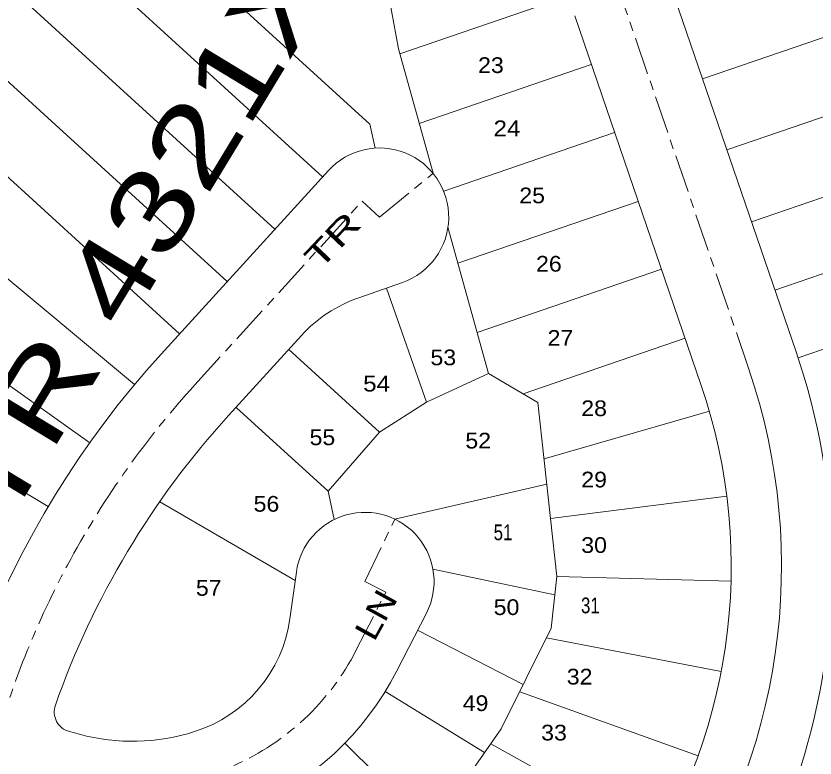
# Model space of a CAD drawing. Extents: x 6387474 to 6390971, y 1972046 to 1973920.
# Drawn here: x 6389237 to 6389745, y 1972779 to 1973251 of the extents above; entities that cross this region are included whole.
import ezdxf

# ---------------------------------------------------------------- set-up
doc = ezdxf.new("R2010")
doc.units = 0
doc.header["$LTSCALE"] = 4
doc.linetypes.add('LONG_DASH_SHORT_DASH', pattern=[9.9, 6, -1.2, 1.5, -1.2])
for name, color, linetype, lineweight in [('1', 7, 'Continuous', 13), ('2', 7, 'LONG_DASH_SHORT_DASH', 13), ('3', 7, 'Continuous', 13), ('4', 7, 'Continuous', 13)]:
    doc.layers.add(name, color=color, linetype=linetype, lineweight=lineweight)
doc.layers.add('7', color=7, linetype='Continuous')

msp = doc.modelspace()

# ---------------------------------------------------------------- linework, layer by layer
at = {"layer": '2'}
for p, q in [((6389702.592, 1973027.135), (6389622.235, 1973261.523)), ((6389467.811, 1973123.262), (6389501.879, 1973151.108)), ((6389458.497, 1972891.565), (6389477.608, 1972931.198)), ((6389471.847, 1972884.725), (6389458.497, 1972891.565)), ((6389453.054, 1972848.049), (6389471.847, 1972884.725))]:
    msp.add_line(p, q, dxfattribs=at)
msp.add_lwpolyline([(6389350.365, 1973016.66), (6389456.724, 1973133.366), (6389467.811, 1973123.262)], dxfattribs=at)
at = {"layer": '2', "linetype": 'Continuous'}
msp.add_arc((6389335.562, 1972901.304), 388, 270.34667, 18.92364, dxfattribs=at)
at = {"layer": '2'}
for centre, radius, start, end in [((6389771.658, 1972632.718), 570, 137.65572, 165.09236), ((6389310.662, 1972921.018), 160, 255.09194, 332.86738)]:
    msp.add_arc(centre, radius, start, end, dxfattribs=at)
at = {"layer": '3'}
for p, q in [((6389461.63, 1973182.312), (6389072.673, 1973536.784)), ((6389431.586, 1973148.835), (6389073.043, 1973475.589)), ((6389401.274, 1973115.575), (6389073.413, 1973414.367)), ((6389370.963, 1973082.315), (6389073.784, 1973353.146)), ((6389479.969, 1973230.272), (6389463.195, 1973318.918)), ((6389340.651, 1973049.055), (6389074.154, 1973291.925)), ((6389587.696, 1973263.794), (6389480.831, 1973227.157)), ((6389784.098, 1973249.169), (6389673.319, 1973211.19)), ((6389501.879, 1973151.108), (6389479.969, 1973230.272)), ((6389602.55, 1973220.269), (6389493.121, 1973182.753)), ((6389311.975, 1973016.765), (6389074.625, 1973214.186)), ((6389797.825, 1973203.344), (6389688.821, 1973165.973)), ((6389461.63, 1973182.312), (6389464.961, 1973167.167)), ((6389617.39, 1973176.982), (6389508.626, 1973139.694)), ((6389811.683, 1973157.078), (6389704.472, 1973120.322)), ((6389632.389, 1973133.232), (6389517.733, 1973093.924)), ((6389283.443, 1972979.771), (6389075.147, 1973127.843)), ((6389537.139, 1973023.81), (6389511.357, 1973116.959)), ((6389824.899, 1973112.959), (6389719.397, 1973076.789)), ((6389647.181, 1973090.087), (6389529.922, 1973049.886)), ((6389497.798, 1973005.508), (6389472.266, 1973078.188)), ((6389837.948, 1973069.396), (6389734.116, 1973033.799)), ((6389257.09, 1972939.344), (6389075.633, 1973047.475)), ((6389662.213, 1973046.242), (6389559.249, 1973010.943)), ((6389467.882, 1972986.489), (6389410.097, 1973039.15)), ((6389497.798, 1973005.508), (6389537.139, 1973023.81)), ((6389537.139, 1973023.81), (6389568.617, 1973005.492)), ((6389467.882, 1972986.489), (6389497.798, 1973005.508)), ((6389568.617, 1973005.492), (6389580.573, 1972894.731)), ((6389435.193, 1972948.919), (6389376.596, 1973002.321)), ((6389572.493, 1972969.58), (6389677.639, 1972999.893)), ((6389435.193, 1972948.919), (6389467.882, 1972986.489)), ((6389477.608, 1972931.198), (6389574.243, 1972953.372)), ((6389435.193, 1972948.919), (6389438.994, 1972931.007)), ((6389576.585, 1972931.671), (6389688.769, 1972945.817)), ((6389327.993, 1972942.301), (6389414.179, 1972892.316)), ((6389579.323, 1972883.05), (6389501.805, 1972899.342)), ((6389577.067, 1972861.964), (6389580.573, 1972894.731)), ((6389580.573, 1972894.731), (6389691.435, 1972891.766)), ((6389545.231, 1972797.842), (6389577.067, 1972861.964)), ((6389492.047, 1972860.553), (6389559.266, 1972826.11)), ((6389573.941, 1972855.667), (6389685.213, 1972834.366)), ((6389534.619, 1972782.798), (6389471.493, 1972821.75)), ((6389556.993, 1972821.533), (6389670.492, 1972780.647)), ((6389545.231, 1972797.842), (6389515.636, 1972755.89)), ((6389498.047, 1972737.54), (6389445.712, 1972788.797)), ((6389538.594, 1972788.433), (6389646.715, 1972728.329))]:
    msp.add_line(p, q, dxfattribs=at)
at = {"layer": '4'}
for p, q in [((6389732.862, 1973037.513), (6389652.505, 1973271.901)), ((6389672.321, 1973016.757), (6389591.964, 1973251.145)), ((6389328.931, 1973036.194), (6389435.29, 1973152.9)), ((6389454.089, 1973071.803), (6389482.394, 1973081.746)), ((6389371.799, 1972997.126), (6389418.209, 1973048.051)), ((6389414.916, 1972897.621), (6389410.787, 1972867.907)), ((6389478.863, 1972834.825), (6389497.656, 1972871.5)), ((6389270.507, 1972796.145), (6389276.96, 1972794.427))]:
    msp.add_line(p, q, dxfattribs=at)
for centre, radius, start, end in [((6389467.811, 1973123.259), 44, 289.35556, 137.65176), ((6389483.251, 1972988.775), 88, 109.35274, 137.65556), ((6389771.661, 1972632.72), 599, 137.65605, 180.34667), ((6389335.562, 1972901.304), 420, 307.91924, 18.92365), ((6389335.562, 1972901.304), 356, 270.34667, 18.92365), ((6389771.658, 1972632.718), 541, 137.65572, 160.52995), ((6389458.497, 1972891.565), 44, 332.86889, 172.08892), ((6389323.625, 1972880.018), 88, 287.54705, 352.08944), ((6389310.662, 1972921.018), 189, 253.67626, 332.86738), ((6389273.852, 1972808.707), 13, 160.52995, 255.09194), ((6389310.662, 1972921.018), 131, 255.09194, 287.55198)]:
    msp.add_arc(centre, radius, start, end, dxfattribs=at)

# ---------------------------------------------------------------- texts
at = {"layer": '1', "width": 1.35}
msp.add_text('TR 4321X', height=50, rotation=58.729, dxfattribs=at).set_placement((6389230.058, 1972925.588))
at = {"layer": '2'}
for s, rotation, width, p in [('TR', 46.476, 1.5, (6389429.582, 1973088.819)), ('LN', 61.114, 1.25, (6389464.372, 1972852.708))]:
    msp.add_text(s, height=15, rotation=rotation, dxfattribs=dict(at, width=width)).set_placement(p)
at = {"layer": '7'}
for s, width, p in [('23', 1.1, (6389530.506, 1973214.886)), ('24', 1.15, (6389540.336, 1973174.703)), ('25', 1.1, (6389556.721, 1973132.058)), ('26', 1.1, (6389567.372, 1973088.595)), ('27', 1.1, (6389574.715, 1973041.435)), ('53', 1.1, (6389500.187, 1973029.061)), ('54', 1.15, (6389457.383, 1973012.382)), ('28', 1.1, (6389596.13, 1972996.725)), ('55', 1.1, (6389423.292, 1972978.265)), ('52', 1.1, (6389522.408, 1972976.158)), ('29', 1.1, (6389596.13, 1972951.402)), ('56', 1.1, (6389387.695, 1972935.962)), ('51', 0.8, (6389540.425, 1972917.845)), ('30', 1.1, (6389596.13, 1972909.754)), ('57', 1.1, (6389350.985, 1972882.527)), ('50', 1.1, (6389540.425, 1972870.27)), ('31', 0.8, (6389595.989, 1972871.367)), ('32', 1.1, (6389586.951, 1972826.085)), ('49', 1.1, (6389520.695, 1972809.223)), ('33', 1.1, (6389570.647, 1972790.516))]:
    msp.add_text(s, height=10, dxfattribs=dict(at, width=width)).set_placement(p)

doc.saveas('drawing.dxf')
